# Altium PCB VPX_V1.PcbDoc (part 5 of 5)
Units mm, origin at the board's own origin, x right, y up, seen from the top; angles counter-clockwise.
Board outline 157.76 x 100.08 mm, 10 copper layers (Top Layer (PADS/SIG), Layer 2 (GND), Layer 3 (SIG), Layer 4 (SIG), Layer 5 (GND), Layer 6 (PWR), Layer 7 (GND), Layer 8 (SIG/PWR), Layer 9 (GND), Bottom Layer (PAD/SIG)), stack 1.614 mm thick; 383 components, 223 nets, 1313 pads, 1223 vias.
Unrouted connection lines stored in the file: 3.
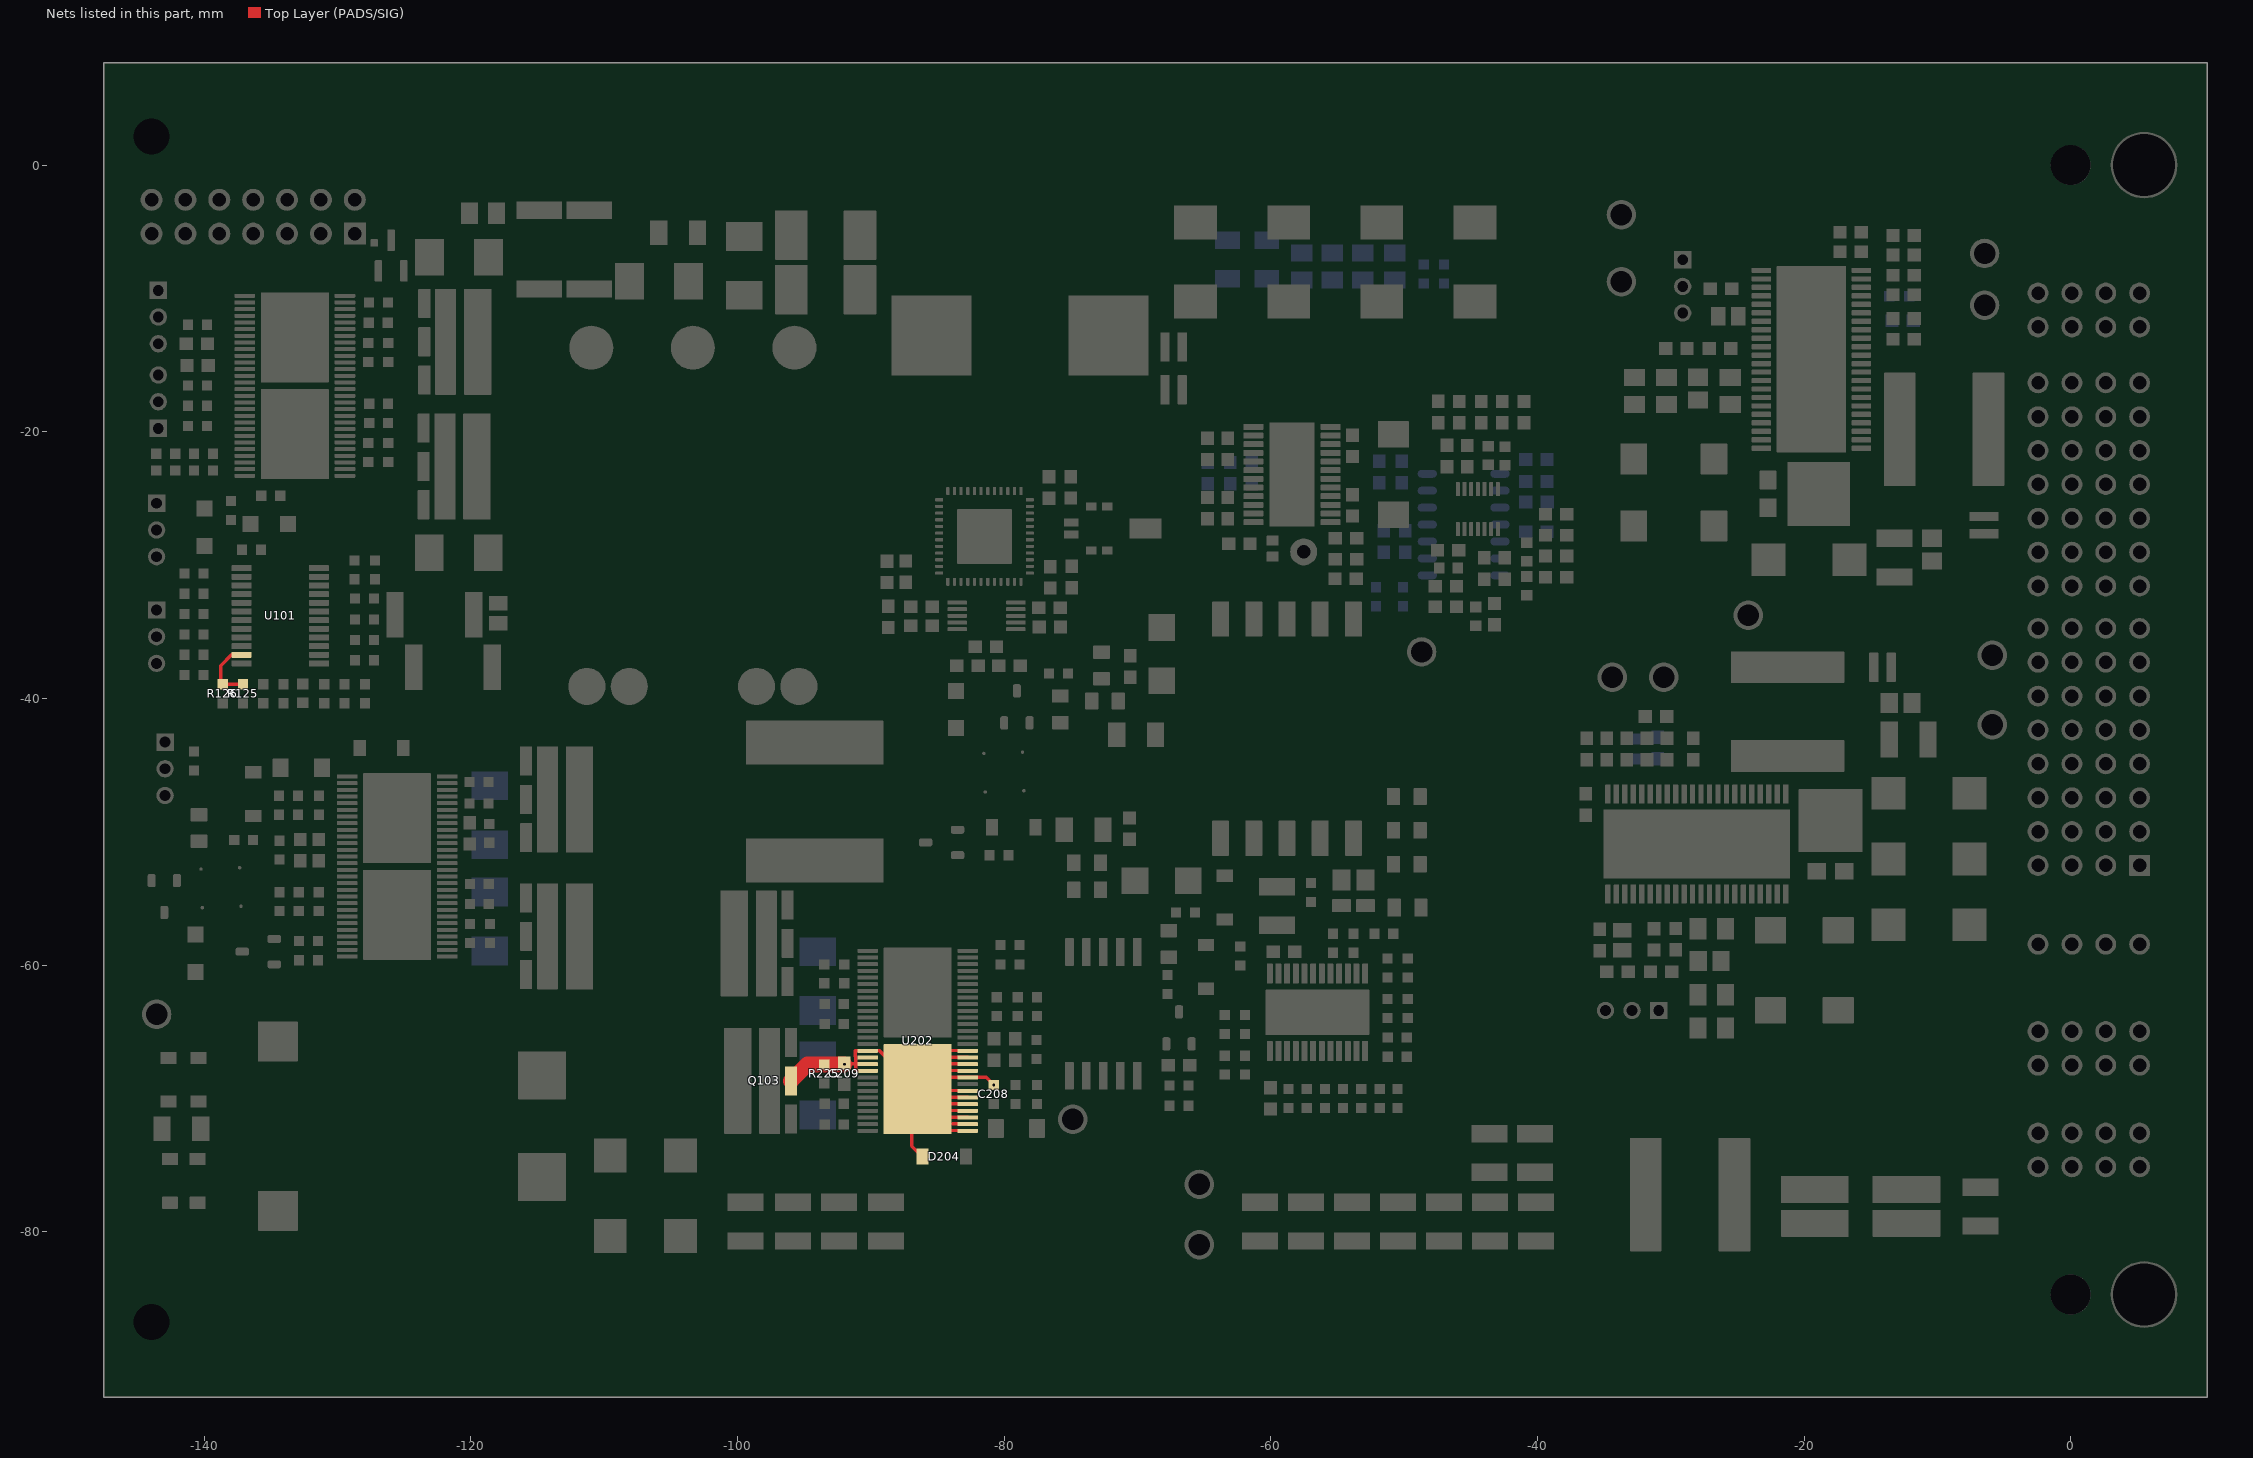
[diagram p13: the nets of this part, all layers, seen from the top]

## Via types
v1: diameter 0.508, hole 0.203, Top Layer (PADS/SIG) to Bottom Layer (PAD/SIG), 943 vias
v2: diameter 0.5, hole 0.2, Top Layer (PADS/SIG) to Bottom Layer (PAD/SIG), tented both sides, 268 vias
v3: diameter 0.5, hole 0.2, Top Layer (PADS/SIG) to Bottom Layer (PAD/SIG), 12 vias

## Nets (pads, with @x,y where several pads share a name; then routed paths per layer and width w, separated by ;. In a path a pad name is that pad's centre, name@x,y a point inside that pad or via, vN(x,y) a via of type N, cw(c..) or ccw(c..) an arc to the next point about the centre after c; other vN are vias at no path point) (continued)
VS_HOB: C208.2 C209.2 D204.2 Q103.5 R225.2 U202.1 U202.2 U202.3 U202.4 U202.5 U202.6 U202.7 U202.9 U202.10 U202.11 U202.12 U202.13 U202.44 U202.45 U202.46 U202.47 U202.57 | length 47.4
  Top Layer (PADS/SIG) w0.254: C209.2@-91.985,-67.446 v1(-91.966,-67.428) -91.946,-67.408 -91.12,-67.408 ; U202.47@-90.235,-67.908 -91.092,-67.908 -91.12,-67.879 -91.12,-67.408 ; U202.46@-90.235,-67.408 -91.12,-67.408 ; U202.57@-86.911,-70.806 -86.911,-73.573 D204.2@-86.122,-74.362 ; U202.57@-86.485,-69.283 -89.36,-66.408 -90.235,-66.408 -91.173,-66.408 -91.173,-66.855 -91.12,-66.908 -91.12,-67.408 ; U202.57@-86.36,-69.408 U202.7@-82.735,-69.408 ; U202.57@-85.86,-69.908 U202.6@-82.735,-69.908 ; U202.57@-85.36,-70.408 U202.5@-82.735,-70.408 ; U202.57@-84.86,-70.908 U202.4@-82.735,-70.908 ; U202.57@-84.61,-67.408 U202.11@-82.735,-67.408 ; U202.57@-84.371,-66.488 -84.291,-66.408 U202.13@-82.735,-66.408 ; U202.57@-84.36,-71.408 U202.3@-82.735,-71.408 ; U202.57@-84.11,-66.908 U202.12@-82.735,-66.908 ; U202.57@-84.032,-72.408 U202.1@-82.735,-72.408 ; -83.86,-71.908 U202.2@-82.735,-71.908 ; U202.10@-82.735,-67.908 -85.11,-67.908 -85.61,-68.408 -82.735,-68.408 -82.717,-68.426 -81.335,-68.426 v1(-80.775,-68.987) ; C208.2@-80.759,-68.971 -80.759,-69.002 -80.521,-69.241 C208.2@-80.49,-69.241
  Top Layer (PADS/SIG) w1.194: Q103.5@-95.979,-68.681 -94.744,-67.446 R225.2@-93.485,-67.446 C209.2@-91.985,-67.446
VSENSE: R125.1 R126.2 U101.23 | length 4.9
  Top Layer (PADS/SIG) w0.254: U101.23@-137.181,-36.731 -137.94,-36.731 -138.752,-37.544 -138.752,-38.785 R126.2@-138.599,-38.937 R125.1@-137.075,-38.937
pads on no net: "MSP430 JTAG.6" "MSP430 JTAG.12" "MSP430 JTAG.14" J1.A1 J1.A2 J1.A3 J1.A4 J1.A5 J1.A6 J1.A7 J1.A8 J1.B1 J1.B2 J1.B3 J1.B4 J1.B5 J1.B6 J1.B7 J1.B8 J1.C1 J1.C2 J1.C3 J1.C4 J1.C6 J1.C7 J1.C8 J1.D1 J1.D2 J1.D3 J1.D4 J1.D6 J1.D7 J1.D8 J2. J4. Q101.2 Q102.2 Q103.2 Q104.2 Q105.2 Q106.2 T1.3 T1.6 T1.7 T1.8 U1.7 U1.8 U1.9 U1.10 U1.11 U1.16 U1.17 U1.18 U1.19 U1.26 U1.27 U1.28 U1.29 U1.30 U1.33 U1.38 U1.39 U1.40 U1.42 U1.43 U1.49@-80.098,-26.483 U1.49@-80.098,-27.853 U1.49@-80.098,-29.223 U1.49@-81.468,-26.483 U1.49@-81.468,-27.853 U1.49@-81.468,-29.223 U1.49@-82.838,-26.483 U1.49@-82.838,-27.853 U1.49@-82.838,-29.223 U4.7 U4.9 U4.37 U7.7 U9.1 U9.8 U201.14 U201.16 U201.43 U202.14 U202.16 U202.43 U203.14 U203.16 U203.43

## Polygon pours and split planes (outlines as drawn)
PGND on Layer 9 (GND) "LAYER_9_(GND)_PGND_P079" (solid, remove dead copper, pour order 79): -1.717,-56.455 10.288,-56.455 10.288,-82.453 9.627,-83.114 -138.102,-83.114 -138.102,-56.4 -138.102,-42.408 -118.323,-42.408 -113.087,-37.104 -92.813,-37.104 -84.182,-45.735 -47.538,-45.735 -46.989,-46.284 -46.989,-71.612 -16.874,-71.612 -6.955,-61.692
SGND on Layer 9 (GND) "LAYER_9_(GND)_SGND_P064" (solid, remove dead copper, pour order 64): -0.406,-53.498 5.494,-53.498 5.494,-1.489 -145.204,-1.489 -145.204,-83.165 -139.278,-83.168 -139.108,-82.998 -139.108,-60.068 -139.108,-41.063 -119.189,-41.063 -114.151,-36.025 -93.117,-36.025 -84.422,-44.72 -46.83,-44.72 -45.89,-45.66 -45.89,-70.559 -17.467,-70.559 -8.171,-61.263
PGND on Top Layer (PADS/SIG) "TOP_LAYER_(PADS/SIG)_PGND_P080" (solid, remove dead copper, pour order 80): -1.754,-56.58 10.251,-56.58 10.251,-82.579 9.59,-83.239 -138.14,-83.239 -138.14,-56.525 -138.14,-42.533 -118.36,-42.533 -113.125,-37.23 -92.85,-37.23 -84.22,-45.86 -47.575,-45.86 -47.026,-46.409 -47.026,-71.12 -16.294,-71.12 -6.992,-61.818
Chassis on Top Layer (PADS/SIG) "TOP_LAYER_(PADS/SIG)_CHASSIS_P074" (solid, remove dead copper, pour order 74): 6.561,-53.026 6.307,-52.772 6.307,-1.333 10.117,-1.333 10.117,-56.654 10.216,-56.654 10.262,-56.7 10.262,-89.82 -147.617,-89.842 -147.617,5.33 10.233,5.33 10.262,5.3 10.262,-1.333 -145.331,-1.333 -145.331,-82.991 -3.264,-82.991 -3.159,-83.096 -3.159,-57.854 -1.981,-56.676 2.911,-56.676
3.3V on Top Layer (PADS/SIG) "TOP_LAYER_(PADS/SIG)_3.3V_P002" (solid, remove dead copper, pour order 2): -54.653,-18.863 -47.795,-18.863 -47.795,-22.8 -54.653,-22.8
PVIN on Top Layer (PADS/SIG) "TOP_LAYER_(PADS/SIG)_PVIN_P003" (solid, remove dead copper, pour order 3): -17.493,-70.646 -12.319,-65.472 -12.323,-56.593 -39.786,-56.593 -39.786,-70.646
SGND on Top Layer (PADS/SIG) "TOP_LAYER_(PADS/SIG)_SGND_P070" (solid, remove dead copper, pour order 70): -0.413,-53.526 5.488,-53.526 5.488,-1.517 -145.331,-1.517 -145.331,-83.193 -140.322,-83.196 -139.115,-83.175 -139.115,-60.096 -139.115,-41.091 -119.196,-41.091 -114.158,-36.053 -93.124,-36.053 -84.429,-44.748 -46.837,-44.748 -45.897,-45.688 -45.897,-70.587 -17.473,-70.587 -8.178,-61.291
"Input Return" on Top Layer (PADS/SIG) "TOP_LAYER_(PADS/SIG)_INPUT_RETURN_P068" (solid, remove dead copper, pour order 68): -15.156,-78.299 -4.869,-78.299 -4.869,-71.441 -4.996,-71.314 -4.488,-70.806 7.577,-70.806 7.577,-83.125 7.45,-83.252 -15.156,-83.252
Input_Supply on Top Layer (PADS/SIG) "TOP_LAYER_(PADS/SIG)_INPUT_SUPPLY_P065" (solid, remove dead copper, pour order 65): -15.156,-77.791 -15.156,-71.949 -15.029,-71.949 -2.202,-59.122 6.307,-59.122 6.307,-68.393 4.91,-69.79 -3.218,-69.79 -4.996,-71.568 -4.996,-77.791
3.3V_OUT on Top Layer (PADS/SIG) "TOP_LAYER_(PADS/SIG)_3.3V_OUT_P058" (solid, remove dead copper, pour order 58): -4.8,-35.692 6.815,-24.078 6.815,-14.896 -25.964,-14.896 -25.964,-35.692
"3.3V CS+" on Top Layer (PADS/SIG) "TOP_LAYER_(PADS/SIG)_3.3V_CS+_P057" (solid, remove dead copper, pour order 57): -10.82,-27.005 -10.82,-13.475 -4.768,-13.475 -4.768,-27.005
5V on Top Layer (PADS/SIG) "TOP_LAYER_(PADS/SIG)_5V_P027" (solid, remove dead copper, pour order 27): -12.323,-65.415 -12.323,-34.736 -3.178,-34.736 -3.178,-56.269 -8.171,-61.263
"5V CS+" on Top Layer (PADS/SIG) "TOP_LAYER_(PADS/SIG)_5V_CS+_P028" (solid, remove dead copper, pour order 28): -27.531,-40.025 -27.531,-34.471 -14.328,-34.471 -14.328,-40.025
VIN on Top Layer (PADS/SIG) "TOP_LAYER_(PADS/SIG)_VIN_P026" (solid, remove dead copper, pour order 26): -119.039,-81.28 -119.039,-71.632 -30.734,-71.632 -30.734,-81.28
NetL3_1 on Top Layer (PADS/SIG) "TOP_LAYER_(PADS/SIG)_NETL3_1_P025" (solid, remove dead copper, pour order 25): -29.972,-82.851 -29.972,-72.898 -15.631,-72.898 -15.631,-82.851
PVIN on Top Layer (PADS/SIG) "TOP_LAYER_(PADS/SIG)_PVIN_P024" (solid, remove dead copper, pour order 24): -38.362,-18.215 -38.362,-28.783 -37.533,-29.611 -21.887,-29.611 -21.887,-7.687 -68.316,-7.687 -68.316,-18.215
"12V CS+" on Top Layer (PADS/SIG) "TOP_LAYER_(PADS/SIG)_12V_CS+_P022" (solid, remove dead copper, pour order 22): -67.451,-22.15 -76.157,-22.15 -76.157,-3.369 -67.451,-3.369
NetD1_3 on Top Layer (PADS/SIG) "TOP_LAYER_(PADS/SIG)_NETD1_3_P021" (solid, remove dead copper, pour order 21): -21.637,-19.222 -21.637,-21.012 -21.637,-27.061 -11.213,-27.061 -11.213,-13.589 -16.549,-13.589 -16.549,-19.222
NetD2_3 on Top Layer (PADS/SIG) "TOP_LAYER_(PADS/SIG)_NETD2_3_P019" (solid, remove dead copper, pour order 19): -28.696,-47.824 -28.696,-46.034 -27.138,-46.034 -27.138,-43.995 -25.994,-42.851 -25.982,-42.863 -15.338,-42.863 -15.338,-51.745 -20.673,-51.745 -20.673,-47.824
SW_A on Top Layer (PADS/SIG) "TOP_LAYER_(PADS/SIG)_SW_A_P006" (solid, remove dead copper, pour order 6): -115.218,-39.35 -113.131,-37.264 -106.572,-37.264 -106.572,-41.133 -115.218,-41.133
NetD3_1 on Top Layer (PADS/SIG) "TOP_LAYER_(PADS/SIG)_NETD3_1_P018" (solid, remove dead copper, pour order 18): -112.946,-43.027 -112.946,-37.864 -102.035,-37.864 -101.721,-38.178 -101.721,-63.367 -99.771,-63.367 -98.879,-64.259 -98.879,-73.103 -118.457,-73.103 -118.948,-72.612 -118.948,-62.076 -110.306,-61.922 -110.306,-61.434 -110.306,-52.651 -111.995,-52.651 -113.2,-51.446
NetL301_2 on Top Layer (PADS/SIG) "TOP_LAYER_(PADS/SIG)_NETL301_2_P017" (solid, remove dead copper, pour order 17): -92.515,-37.735 -88.759,-41.491 -88.759,-45.248 -100.631,-45.248 -100.631,-37.735
NetC117_2 on Top Layer (PADS/SIG) "TOP_LAYER_(PADS/SIG)_NETC117_2_P016" (solid, remove dead copper, pour order 16): -117.653,-39.5 -116.925,-38.775 -116.925,-31.744 -121.272,-31.744 -121.272,-39.5
NetC117_1 on Top Layer (PADS/SIG) "TOP_LAYER_(PADS/SIG)_NETC117_1_P008" (solid, pour order 8): -120.964,-18.804 -120.323,-18.164 -120.323,-18.124 -99.253,-18.124 -99.23,-18.101 -99.484,-17.847 -99.484,-11.673 -100.109,-11.673 -101.734,-10.048 -101.734,-7.56 -95.895,-7.56 -91.71,-11.745 -91.71,-32.813 -118.158,-32.813 -120.964,-30.006 -120.964,-18.754
NetL101_1 on Top Layer (PADS/SIG) "TOP_LAYER_(PADS/SIG)_NETL101_1_P015" (solid, remove dead copper, pour order 15): -91.737,-19.59 -91.737,-9.551 -80.264,-9.551 -80.264,-19.59
NetL101_1 on Top Layer (PADS/SIG) "TOP_LAYER_(PADS/SIG)_NETL101_1_P014" (solid, remove dead copper, pour order 14): -106.385,-20.378 -106.385,-11.673 -99.484,-11.673 -99.484,-20.378
NetC118_1 on Top Layer (PADS/SIG) "TOP_LAYER_(PADS/SIG)_NETC118_1_P013" (solid, remove dead copper, pour order 13): -117.109,-2.077 -117.205,-2.173 -117.205,-11.14 -116.672,-11.673 -110.025,-11.673 -110.025,-8.517 -107.004,-5.537 -107.004,-17.419 -120.715,-17.419 -120.715,-2.077
NetC118_2 on Top Layer (PADS/SIG) "TOP_LAYER_(PADS/SIG)_NETC118_2_P012" (solid, remove dead copper, pour order 12): -118.661,-10.386 -118.661,-2.187 -108.882,-2.187 -108.882,-10.386
NetC122_1 on Top Layer (PADS/SIG) "TOP_LAYER_(PADS/SIG)_NETC122_1_P011" (solid, remove dead copper, pour order 11): -105.518,-11.511 -105.518,-2.806 -93.449,-2.806 -93.449,-11.511
NetC44_1 on Top Layer (PADS/SIG) "TOP_LAYER_(PADS/SIG)_NETC44_1_P001" (solid, remove dead copper, pour order 1): -73.195,-44.009 -73.195,-37.635 -66.429,-37.635 -66.429,-44.009
NetC49_1 on Top Layer (PADS/SIG) "TOP_LAYER_(PADS/SIG)_NETC49_1_P010" (solid, remove dead copper, pour order 10): -75.037,-54.629 -75.037,-48.931 -68.623,-48.931 -68.623,-54.629
Input_Supply on Layer 8 (SIG/PWR) "LAYER_8_(SIG/PWR)_INPUT_SUPPLY_P071" (solid, remove dead copper, pour order 71): -34.46,-71.695 -16.934,-71.695 -1.821,-56.582 9.609,-56.582 9.609,-82.871 9.228,-83.252 -34.46,-83.252
VIN on Layer 8 (SIG/PWR) "LAYER_8_(SIG/PWR)_VIN_P054" (solid, remove dead copper, pour order 54): -31.482,-83.252 -138.146,-83.252 -138.146,-56.538 -138.146,-42.547 -118.367,-42.547 -113.131,-37.243 -92.857,-37.243 -84.226,-45.873 -47.582,-45.873 -47.033,-46.422 -47.033,-71.75 -31.609,-71.75
PVIN on Layer 8 (SIG/PWR) "LAYER_8_(SIG/PWR)_PVIN_P041" (solid, remove dead copper, pour order 41): -46.83,-44.72 -45.89,-45.66 -45.89,-70.559 -17.467,-70.559 -8.171,-61.263 -32.932,-61.263 -33.53,-60.666 -33.53,-28.497 9.609,-28.348 9.609,-1.502 9.597,-1.489 9.476,-1.61 -145.519,-1.61 -145.193,-83.057 -139.108,-83.057 -139.108,-60.068 -139.108,-41.096 -119.223,-41.096 -114.151,-36.025 -93.117,-36.025 -84.422,-44.72
3.3V_OUT on Layer 8 (SIG/PWR) "LAYER_8_(SIG/PWR)_3.3V_OUT_P039" (solid, remove dead copper, pour order 39): -3.21,-28.436 -6.824,-28.436 -14.569,-36.181 -15.171,-36.181 -33.564,-36.181 -33.564,-13.859 9.576,-13.859 9.576,-27.691 -2.608,-27.691 -3.21,-28.294
5V on Layer 8 (SIG/PWR) "LAYER_8_(SIG/PWR)_5V_P040" (solid, remove dead copper, pour order 40): -33.802,-27.768 -33.802,-61.263 -8.171,-61.263 -0.406,-53.498 9.597,-53.498 9.597,-27.768
SGND on Bottom Layer (PAD/SIG) "BOTTOM_LAYER_(PAD/SIG)_SGND_P062" (solid, remove dead copper, pour order 62): -0.406,-53.498 5.494,-53.498 5.494,-1.489 -145.458,-1.489 -145.458,-83.165 -139.278,-83.168 -139.108,-82.998 -139.108,-60.068 -139.108,-41.063 -119.189,-41.063 -114.151,-36.025 -93.117,-36.025 -84.422,-44.72 -46.83,-44.72 -45.89,-45.66 -45.89,-70.559 -17.467,-70.559 -8.171,-61.263
Chassis on Bottom Layer (PAD/SIG) "BOTTOM_LAYER_(PAD/SIG)_CHASSIS_P056" (solid, remove dead copper, pour order 56): 6.561,-53.026 6.307,-52.772 6.307,-1.333 10.117,-1.333 10.117,-56.654 10.216,-56.654 10.262,-56.7 10.262,-89.82 -147.617,-89.842 -147.617,5.33 10.233,5.33 10.262,5.3 10.262,-1.333 -145.204,-1.333 -145.204,-82.991 -3.264,-82.991 -3.159,-83.096 -3.159,-57.854 -1.981,-56.676 2.911,-56.676
PGND on Bottom Layer (PAD/SIG) "BOTTOM_LAYER_(PAD/SIG)_PGND_P067" (solid, remove dead copper, pour order 67): -1.762,-56.593 10.243,-56.593 10.243,-82.591 9.583,-83.252 -138.092,-83.252 -138.092,-42.546 -118.367,-42.546 -113.132,-37.243 -92.857,-37.243 -84.227,-45.873 -47.583,-45.873 -47.034,-46.422 -47.034,-71.75 -16.918,-71.75 -6.999,-61.831
NetL101_1 on Bottom Layer (PAD/SIG) "BOTTOM_LAYER_(PAD/SIG)_NETL101_1_P038" (solid, remove dead copper, pour order 38): -106.385,-20.42 -106.385,-11.662 -80.264,-11.662 -80.264,-20.42
3.3V on Layer 6 (PWR) "LAYER_6_(PWR)_3.3V_P037" (solid, remove dead copper, pour order 37): -68.978,-36.341 -68.48,-35.843 -68.48,-24.197 -38.288,-24.197 -38.232,-17.377 -39.54,-16.069 -88.506,-16.069 -88.506,-33.524 -85.64,-36.39
Input_Supply on Layer 6 (PWR) "LAYER_6_(PWR)_INPUT_SUPPLY_P073" (solid, remove dead copper, pour order 73): -34.46,-71.695 -16.934,-71.695 -1.821,-56.582 9.609,-56.582 9.609,-82.871 9.228,-83.252 -34.46,-83.252
+12Vp on Layer 6 (PWR) "LAYER_6_(PWR)_+12VP_P072" (solid, remove dead copper, pour order 72): -31.482,-83.252 -138.146,-83.252 -138.146,-56.538 -138.146,-42.547 -118.367,-42.547 -113.131,-37.243 -92.857,-37.243 -84.226,-45.873 -47.582,-45.873 -47.033,-46.422 -47.033,-71.75 -31.609,-71.75
5V on Layer 6 (PWR) "LAYER_6_(PWR)_5V_P046" (solid, remove dead copper, pour order 46): -26.713,-27.768 -26.713,-62.297 -9.205,-62.297 -8.171,-61.263 -0.406,-53.498 9.597,-53.498 9.597,-27.768
+12Vs on Layer 6 (PWR) "LAYER_6_(PWR)_+12VS_P020" (solid, remove dead copper, pour order 20): -42.334,-44.72 -42.334,-22.863 -60.02,-22.863 -62.491,-20.393 -68.077,-20.393 -68.396,-20.712 -68.396,-36.344 -85.686,-36.344 -88.698,-33.332 -88.698,-1.702 -145.458,-1.702 -145.458,-82.998 -139.108,-82.998 -139.108,-60.068 -139.108,-41.063 -119.189,-41.063 -114.151,-36.025 -93.244,-36.025 -84.549,-44.72
PVIN on Layer 6 (PWR) "LAYER_6_(PWR)_PVIN_P048" (solid, remove dead copper, pour order 48): -86.836,-42.433 -84.498,-44.771 -46.779,-44.771 -45.89,-45.66 -45.89,-70.607 -17.497,-70.607 -0.551,-53.661 9.609,-53.661 9.609,-1.502 9.597,-1.489 9.476,-1.61 -88.702,-1.61
3.3V_OUT on Layer 6 (PWR) "LAYER_6_(PWR)_3.3V_OUT_P047" (solid, remove dead copper, pour order 47): -3.178,-28.499 -6.791,-28.499 -14.536,-36.245 -15.138,-36.245 -26.713,-36.245 -26.713,-13.923 9.609,-13.923 9.609,-27.755 -2.575,-27.755 -3.178,-28.358
PGND on Layer 5 (GND) "LAYER_5_(GND)_PGND_P077" (solid, remove dead copper, pour order 77): -1.774,-56.517 10.231,-56.517 10.231,-82.515 9.571,-83.176 -138.159,-83.176 -138.159,-56.462 -138.159,-42.47 -118.379,-42.47 -113.144,-37.167 -92.869,-37.167 -84.239,-45.797 -47.595,-45.797 -47.046,-46.346 -47.046,-71.674 -16.93,-71.674 -7.011,-61.754
SGND on Layer 5 (GND) "LAYER_5_(GND)_SGND_P061" (solid, remove dead copper, pour order 61): -0.406,-53.498 5.494,-53.498 5.494,-1.489 -145.331,-1.489 -145.331,-83.165 -139.108,-83.169 -139.108,-60.068 -139.108,-41.063 -119.189,-41.063 -114.151,-36.025 -93.117,-36.025 -84.422,-44.72 -46.83,-44.72 -45.89,-45.66 -45.89,-70.559 -17.467,-70.559 -8.171,-61.263
PGND on Layer 7 (GND) "LAYER_7_(GND)_PGND_P078" (solid, remove dead copper, pour order 78): -1.732,-56.474 10.273,-56.474 10.273,-82.472 9.613,-83.133 -138.117,-83.133 -138.117,-56.419 -138.117,-42.427 -118.338,-42.427 -113.102,-37.123 -92.827,-37.123 -84.197,-45.754 -47.553,-45.754 -47.004,-46.303 -47.004,-71.631 -16.889,-71.631 -6.969,-61.711
SGND on Layer 7 (GND) "LAYER_7_(GND)_SGND_P063" (solid, remove dead copper, pour order 63): -0.406,-53.498 5.494,-53.498 5.494,-1.489 -145.331,-1.489 -145.331,-83.165 -139.235,-83.168 -139.235,-59.941 -139.235,-41.063 -119.189,-41.063 -114.151,-36.025 -93.117,-36.025 -84.422,-44.72 -46.83,-44.72 -45.89,-45.66 -45.89,-70.559 -17.467,-70.559 -8.171,-61.263
PGND on Layer 3 (SIG) "LAYER_3_(SIG)_PGND_P066" (solid, remove dead copper, pour order 66): -1.761,-56.593 10.244,-56.593 10.244,-82.592 9.584,-83.252 -138.146,-83.252 -138.146,-56.538 -138.146,-42.547 -118.367,-42.547 -113.131,-37.243 -92.857,-37.243 -84.226,-45.873 -47.582,-45.873 -47.033,-46.422 -47.033,-71.75 -16.918,-71.75 -6.998,-61.831
SGND on Layer 3 (SIG) "LAYER_3_(SIG)_SGND_P059" (solid, remove dead copper, pour order 59): -0.406,-53.549 5.494,-53.549 5.494,-1.54 -145.331,-1.54 -145.331,-83.215 -139.108,-83.219 -139.108,-60.119 -139.108,-41.113 -119.189,-41.113 -114.151,-36.075 -93.117,-36.075 -84.422,-44.771 -46.83,-44.771 -45.89,-45.711 -45.89,-70.609 -17.467,-70.609 -8.171,-61.314
PGND on Layer 4 (SIG) "LAYER_4_(SIG)_PGND_P076" (solid, remove dead copper, pour order 76): -1.767,-56.531 10.238,-56.531 10.238,-82.529 9.578,-83.19 -138.152,-83.19 -138.152,-56.476 -138.152,-42.484 -118.372,-42.484 -113.137,-37.18 -92.862,-37.18 -84.232,-45.811 -47.588,-45.811 -47.039,-46.36 -47.039,-71.688 -16.923,-71.688 -7.004,-61.768
SGND on Layer 4 (SIG) "LAYER_4_(SIG)_SGND_P060" (solid, remove dead copper, pour order 60): -0.406,-53.498 5.494,-53.498 5.494,-1.489 -145.458,-1.489 -145.458,-83.165 -139.108,-83.169 -139.108,-60.068 -139.108,-41.063 -119.189,-41.063 -114.151,-36.025 -93.117,-36.025 -84.422,-44.72 -46.83,-44.72 -45.89,-45.66 -45.89,-70.559 -17.467,-70.559 -8.171,-61.263
PGND on Layer 2 (GND) "LAYER_2_(GND)_PGND_P075" (solid, remove dead copper, pour order 75): -1.752,-56.585 10.253,-56.585 10.253,-82.583 9.592,-83.243 -138.137,-83.243 -138.137,-56.53 -138.137,-42.538 -118.358,-42.538 -113.122,-37.234 -92.848,-37.234 -84.217,-45.864 -47.573,-45.864 -47.024,-46.413 -47.024,-71.741 -16.909,-71.741 -6.99,-61.822
SGND on Layer 2 (GND) "LAYER_2_(GND)_SGND_P053" (solid, remove dead copper, pour order 53): -0.406,-53.498 5.494,-53.498 5.494,-1.489 -145.331,-1.489 -145.331,-83.165 -139.151,-83.169 -139.108,-83.125 -139.108,-41.063 -119.189,-41.063 -114.151,-36.025 -93.117,-36.025 -84.422,-44.72 -46.83,-44.72 -45.89,-45.66 -45.89,-70.559 -17.467,-70.559 -8.171,-61.263

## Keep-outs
Keep-Out Layer:
  text ".Layer_Name" at -195.191,-114.202 h1.52

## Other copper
Top Layer (PADS/SIG):
  region net NetR55_1: -54.812,-61.411 -54.812,-58.617 -55.701,-58.617 -55.701,-61.411
  region net NetR51_1: -53.418,-61.411 -53.418,-58.617 -54.434,-58.617 -54.434,-61.411
  region net VLDO: -58.879,-61.411 -57.609,-61.411 -57.609,-59.684 -58.133,-59.159 -58.456,-59.159 -58.879,-59.598
  text ".Layer_Name" at -195.191,-114.202 h1.52
Bottom Layer (PAD/SIG):
  text ".Layer_Name" at -195.191,-114.202 h1.52

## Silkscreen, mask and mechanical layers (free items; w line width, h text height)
Top Overlay:
  lines w0.254: -147.515,-89.602 -147.515,5.133 ; -147.39,5.14 -3.164,5.116 ; -147.345,-83.087 -3.174,-83.176 ; -147.246,-89.856 -3.177,-89.851 ; -147.109,-1.629 -3.136,-1.651
  text "'.PRJ_Number'.PCB_Rev" at -122.471,-86.681 h3.05
  text ".Layer_Name" at -195.191,-114.202 h1.52
Bottom Overlay:
  text ".Layer_Name" at -195.191,-114.202 h1.52
Top Paste:
  text ".Layer_Name" at -195.191,-114.202 h1.52
Bottom Paste:
  text ".Layer_Name" at -195.191,-114.202 h1.52
Top Solder:
  text ".Layer_Name" at -195.191,-114.202 h1.52
  text ".Layer_Name" at -195.191,-114.202 h1.52
Bottom Solder:
  text ".Layer_Name" at -195.191,-114.202 h1.52
Drill Guide:
  text ".Layer_Name" at -195.191,-114.202 h1.52
M1 Board Outline:
  lines w0.254: -147.54,7.642 10.117,7.642 ; -147.526,-92.358 10.244,-92.358 ; -147.515,-92.396 -147.515,7.68 ; 10.244,-92.362 10.244,-71.505 10.244,-30.23 10.244,7.68
  text ".Layer_Name" at -195.191,-114.202 h1.52
M2 Board Dimensions:
  rectangle: -209.847,-99.381 -206.672,-96.206
  rectangle: -206.672,-102.556 -197.147,-99.381
  lines w0.178: -209.847,-99.381 -184.447,-99.381 ; -206.672,-102.556 -206.672,-96.206 ; -203.497,-102.556 -203.497,-96.206 ; -197.147,-102.556 -197.147,-96.206 ; -190.797,-102.556 -190.797,-96.206 ; -209.847,-102.556 -184.447,-102.556 -184.447,-96.206 -209.847,-96.206 -209.847,-102.556
  lines w0.254: -147.479,0.035 10.117,0.035
  text "0.00" at 3.64,8.315 h1.02 r90
  text "0.00" at 21.801,0.314 h1.02
  text ".Layer_Name" at -195.191,-114.202 h1.52
M3 3D STEP Top:
  text ".Layer_Name" at -195.191,-114.202 h1.52
M4 3D STEP Bottom:
  text ".Layer_Name" at -195.191,-114.202 h1.52
M5 Assembly Top:
  lines w0.254: -217.264,-116.022 -49.624,-116.022 ; -217.264,-110.858 -49.573,-110.858 ; -217.264,-105.693 -217.264,-121.187 -115.537,-121.187 -49.573,-121.187 -49.573,-105.693 -217.251,-105.693 -217.251,-121.187 -177.233,-121.187 ; -154.653,-121.187 -154.653,-105.693 ; -122.471,-110.858 -122.471,-105.693 ; -101.135,-110.858 -101.135,-105.693 ; -85.336,-121.352 -85.336,-116.2
  text "COMPONENTS MARKED 'DNP' SHOULD NOT BE POPULATED." at -180.548,-100.486 h1.02
  text "ASSEMBLY VARIANT:" at -180.561,-103.42 h1.02
  text ".VariantName" at -154.246,-103.42 h1.02
  text "PCB VIEWED FROM TOP SIDE" at -215.651,-109.05 h1.52
  text "BOARD #:" at -152.748,-109.05 h1.52
  text ".PRJ_Number" at -138.892,-109.05 h1.52
  text "REV:" at -117.442,-109.05 h1.52
  text ".PCB_Rev" at -110.038,-109.05 h1.52
  text "SVN REV:" at -96.157,-109.05 h1.52
  text ".VersionControl_RevNumber" at -83.304,-109.05 h1.52
  text "TID #:" at -152.748,-114.215 h1.52
  text ".TID" at -138.892,-114.215 h1.52
  text "PLOT NAME =" at -215.651,-119.43 h1.52
  text ".plot_File_Name" at -195.191,-119.43 h1.52
  text "GENERATED    :" at -152.697,-119.43 h1.52
  text ".Print_Date" at -130.612,-119.43 h1.52
  text ".Print_Time" at -112.095,-119.43 h1.52
  text "TEXAS INSTRUMENTS" at -79.977,-119.43 h1.52
M6 Assembly Bottom:
  lines w0.254: -217.276,-110.87 -49.586,-110.87 ; -217.226,-116.035 -49.586,-116.035 ; -181.513,-121.365 -181.513,-116.213 ; -165.714,-110.87 -165.714,-105.706 ; -144.378,-110.87 -144.378,-105.706 ; -112.197,-121.2 -112.197,-105.706 ; -89.616,-121.2 -49.598,-121.2 -49.598,-105.706 -217.276,-105.706 -217.276,-121.2 -151.313,-121.2 -49.586,-121.2 -49.586,-105.706
  text "COMPONENTS MARKED 'DNP' SHOULD NOT BE POPULATED." at -54.856,-100.473 h1.02
  text ".VariantName" at -81.374,-103.42 h1.02
  text "ASSEMBLY VARIANT:" at -54.983,-103.42 h1.02
  text ".VersionControl_RevNumber" at -183.545,-109.063 h1.52
  text "SVN REV:" at -170.693,-109.063 h1.52
  text ".PCB_Rev" at -156.812,-109.063 h1.52
  text "REV:" at -149.408,-109.063 h1.52
  text ".PRJ_Number" at -127.957,-109.063 h1.52
  text "BOARD #:" at -114.102,-109.063 h1.52
  text "PCB VIEWED FROM BOTTOM SIDE" at -51.199,-109.063 h1.52
  text ".TID" at -127.957,-114.227 h1.52
  text "TID #:" at -114.102,-114.227 h1.52
  text "TEXAS INSTRUMENTS" at -186.873,-119.443 h1.52
  text ".Print_Time" at -154.754,-119.443 h1.52
  text ".Print_Date" at -136.238,-119.443 h1.52
  text "GENERATED    :" at -114.152,-119.443 h1.52
  text ".plot_File_Name" at -71.658,-119.443 h1.52
  text "PLOT NAME =" at -51.199,-119.443 h1.52
M9 Title Sheet:
  drawing of 57 lines, arcs and shapes, not listed
  text "1" at -191.055,111.731 h1.78
  text "2" at -127.665,111.731 h1.78
  text "3" at -64.436,111.731 h1.78
  text "4" at -0.767,111.731 h1.78
  text "5" at 62.708,111.731 h1.78
  text "6" at 126.335,111.731 h1.78
  text "A" at -220.426,82.699 h1.78
  text "A" at 155.494,82.699 h1.78
  text "B" at -220.426,22.247 h1.78
  text "B" at 155.494,22.247 h1.78
  text "C" at -220.426,-38.078 h1.78
  text "C" at 155.494,-38.078 h1.78
  text "PROJECT TITLE:" at 78.278,-85.348 h1.14
  text ".PRJ_Title" at 79.548,-88.734 h1.78
  text "DESIGNED FOR:" at 78.278,-92.993 h1.14
  text ".PRJ_Customer" at 79.548,-96.549 h1.78
  text "D" at -220.426,-98.276 h1.78
  text "D" at 155.494,-98.276 h1.78
  text "FILE NAME:" at 78.278,-100.613 h1.14
  text ".PCB_File_Name_No_Path" at 79.548,-103.661 h1.78
  text "Texas Instruments (TI) and/or its licensors do not warrant the accuracy or completeness of this specification" at -47.947,-107.772 h1.14
  text "ENGINEER:" at 78.278,-107.979 h1.14
  text "LAYOUT BY:" at 116.505,-107.979 h1.14
  text "or any information contained therein. TI and/or its licensors do not warrant that this design will meet" at -49.09,-110.633 h1.14
  text ".PRJ_Engineer" at 79.548,-111.916 h1.78
  text ".PCB_Layout" at 117.788,-111.916 h1.78
  text "the specifications, will be suitable for your application or fit for any particular purpose, or will operate in" at -49.09,-113.495 h1.14
  text ".Layer_Name" at -195.191,-114.202 h1.52
  text "ALTIUM DESIGNER VERSION:" at 116.505,-115.853 h1.14
  text "an implementation. TI and/or its licensors do not warrant that the design is production worthy. You should" at -49.09,-116.357 h1.14
  text "completely validate and test your design implementation to confirm the system functionality for your application." at -47.947,-119.218 h1.14
  text ".print_Scale" at 79.548,-119.239 h1.78
  text ".Application_BuildNumber" at 117.788,-119.239 h1.78
  text "1" at -191.055,-124.489 h1.78
  text "2" at -127.665,-124.489 h1.78
  text "3" at -64.436,-124.489 h1.78
  text "4" at -0.767,-124.489 h1.78
  text "5" at 62.708,-124.489 h1.78
  text "6" at 126.335,-124.489 h1.78
M10 Fab Notes:
  drawing of 189 lines, arcs and shapes, not listed
  text "DESIGN INFORMATION" at 104.656,69.051 h1.52
  text "MIN. TRACK WIDTH:" at 88.284,65.695 h1.52
  text "8" at 116.129,65.695 h1.52
  text "MIL" at 120.06,65.695 h1.52
  text "7.874" at 111.903,62.604 h1.52
  text "MIN. CLEARANCE:" at 88.284,62.542 h1.52
  text "MIL" at 120.06,62.542 h1.52
  text "MIN. VIA PAD SIZE:" at 88.284,59.389 h1.52
  text "24" at 115.367,59.389 h1.52
  text "MIL" at 120.06,59.389 h1.52
  text "0.05mm (2MIL)" at 105.937,56.09 h1.52
  text "MINIMUM ANNULAR RING" at 79.922,55.881 h1.52
  text "EXTERNAL" at 123.921,55.881 h1.52
  text "PER" at 85.002,53.084 h1.52
  text "IPC-D-275 CLASS 2 LEVEL C" at 90.59,53.084 h1.52
  text "MIL, HOLES" at 128.391,50.531 h1.52
  text "+/-" at 118.423,50.313 h1.52
  text "+/-" at 140.114,50.313 h1.52
  text "REGISTRATION TOLERANCES:" at 79.922,50.286 h1.52
  text "METAL" at 110.396,50.286 h1.52
  text "5" at 125.032,50.286 h1.52
  text "3" at 146.19,50.286 h1.52
  text "MIL" at 149.143,50.286 h1.52
  text "HOLE SIZE TOLERANCE (UNLESS OTHERWISE SPECIFIED):" at 79.922,47.789 h1.52
  text "+/-" at 140.114,47.716 h1.52
  text "3" at 146.19,47.689 h1.52
  text "MIL" at 149.143,47.689 h1.52
  text "MATERIAL:" at 78.023,44.193 h1.52
  text "FR-4 High Tg" at 103.079,40.928 h1.52
  text "FR-4" at 88.716,40.611 h1.52
  text "OTHER" at 126.511,40.611 h1.52
  text "62 MIL (1.6mm) +/-10%" at 96.847,36.978 h1.52
  text "THICKNESS:" at 79.922,36.769 h1.52
  text "OTHER" at 129.483,36.769 h1.52
  text "TOLERANCE:" at 79.922,33.256 h1.52
  text "ANSI IPC-6012 TYPE 3 CLASS 2" at 105.989,33.256 h1.52
  text "OTHER +/-" at 105.988,29.593 h1.52
  text "BOW & TWIST:" at 79.922,25.906 h1.52
  text "ANSI IPC-6012 TYPE 3 CLASS 2" at 105.989,25.906 h1.52
  text "OTHER +/-" at 105.988,22.179 h1.52
  text "DRILLING:" at 78.023,18.862 h1.52
  text "NC_DRILL FILES" at 122.752,16.19 h1.52
  text "REFERENCE:" at 79.922,16.09 h1.52
  text "AS SHOWN" at 101.137,16.09 h1.52
  text "OTHER" at 130.321,12.477 h1.52
  text "PTH COPPER THICKNESS:" at 79.914,12.387 h1.52
  text "20-30 um" at 112.101,12.387 h1.52
  text "BOARD FINISH:" at 78.023,8.638 h1.52
  text "SILKSCREEN:" at 81.966,5.841 h1.52
  text "TOP" at 109.265,5.841 h1.52
  text "BOTTOM" at 122.244,5.841 h1.52
  text "SILKSCREEN COLOR:" at 81.966,1.899 h1.52
  text "WHITE" at 109.265,1.899 h1.52
  text "OTHER" at 122.244,1.899 h1.52
  text "GREEN" at 112.592,-1.744 h1.52
  text "OTHER" at 128.289,-1.744 h1.52
  text "SOLDER RESIST COLOR:" at 81.966,-1.919 h1.52
  text "MATTE" at 112.592,-5.662 h1.52
  text "SEMI-GLOSS" at 128.278,-5.679 h1.52
  text "IMMERSION GOLD (ENIG)" at 104.972,-10.051 h1.52
  text "ENEPIG" at 138.946,-10.234 h1.52
  text "SURFACE FINISH:" at 78.023,-10.26 h1.52
  text "IMM. TIN/SILVER OR EQUIV" at 86.393,-13.747 h1.52
  text "OTHER" at 122.752,-13.847 h1.52
  text "ARRAY/PANEL:" at 78.023,-17.794 h1.52
  text "CUT AND TRIM PER M1 BOARD OUTLINE" at 104.972,-18.003 h1.52
  text "N.C. ROUTE" at 104.972,-21.456 h1.52
  text "V. SCORE" at 126.969,-21.456 h1.52
  text "CERTIFICATION:" at 78.023,-24.736 h1.52
  text "MATERIALS AND WORKMANSHIP FOR ALL PCBS" at 96.438,-24.736 h1.52
  text "TO MEET OR EXCEED THE REQUIREMENTS OF:" at 96.438,-27.125 h1.52
  text "ANSI IPC-A-600F CLASS ->" at 90.482,-30.393 h1.52
  text "2" at 135.135,-30.393 h1.52
  text "1" at 127.134,-30.431 h1.52
  text "3" at 144.126,-30.431 h1.52
  text "RoHS" at 111.106,-34.144 h1.52
  text "OTHER" at 127.474,-34.144 h1.52
  text "PER ORDER" at 137.56,-34.144 h1.52
  text "ALL BOARDS MUST MEET OR EXCEED UL94-V0 REQUIREMENTS." at 78.722,-38.051 h1.52
  text "PCB MUST BEAR THE UL94V-0 UL REGISTERED MATERIAL ID NUMBER" at 78.722,-40.999 h1.52
  text "ADDITIONAL REQUIREMENTS:" at 78.023,-45.302 h1.52
  text "MICROSECTION:" at 79.922,-48.023 h1.52
  text "YES" at 102.928,-48.023 h1.52
  text "REQUIRED" at 124.81,-51.69 h1.52
  text "BARE BOARD ELEC. TEST:" at 79.922,-51.762 h1.52
  text "NONE" at 113.088,-51.762 h1.52
  text "PER ORDER" at 139.846,-51.762 h1.52
  text "XX MIL VIAS REQUIRE NON-CONDUCTIVE FILL AND PLANARIZE" at 84.193,-56.968 h1.5
  text "XX MIL VIAS REQUIRE CONDUCTIVE FILL AND PLANARIZE" at 84.396,-59.609 h1.52
  text "OUTER XX MIL TRACES REQUIRE 50 OHM SINGLE-ENDED IMPEDANCE" at 84.371,-63.759 h1.47
  text "LAYER 2 & 3 (INNER LAYERS) XX MIL WIDE, XX MIL SPACE / TRACES REQUIRE 100 OHM DIFFERENTIAL IMPEDANCE" at 84.168,-69.746 h1.52
  text ".Layer_Name" at -195.191,-114.202 h1.52
M11 Gerber Information:
  lines w0.254: -217.264,-116.022 -49.624,-116.022 ; -217.264,-110.858 -49.573,-110.858 ; -217.264,-105.693 -217.264,-121.187 -115.537,-121.187 -49.573,-121.187 -49.573,-105.693 -217.251,-105.693 -217.251,-121.187 -177.233,-121.187 ; -154.653,-121.187 -154.653,-105.693 ; -122.471,-110.858 -122.471,-105.693 ; -101.135,-110.858 -101.135,-105.693 ; -85.336,-121.352 -85.336,-116.2
  text "ALL ARTWORK VIEWED FROM TOP SIDE" at -215.651,-109.05 h1.52
  text "BOARD #:" at -152.748,-109.05 h1.52
  text ".PRJ_Number" at -138.892,-109.05 h1.52
  text "REV:" at -117.442,-109.05 h1.52
  text ".PCB_Rev" at -110.038,-109.05 h1.52
  text "SVN REV:" at -96.157,-109.05 h1.52
  text ".VersionControl_RevNumber" at -83.304,-109.05 h1.52
  text "LAYER NAME =" at -215.651,-114.202 h1.52
  text "TID #:" at -152.748,-114.215 h1.52
  text ".TID" at -138.892,-114.215 h1.52
  text "PLOT NAME =" at -215.651,-119.43 h1.52
  text ".plot_File_Name" at -195.191,-119.43 h1.52
  text "GENERATED    :" at -152.697,-119.43 h1.52
  text ".Print_Date" at -130.612,-119.43 h1.52
  text ".Print_Time" at -112.095,-119.43 h1.52
  text "TEXAS INSTRUMENTS" at -79.977,-119.43 h1.52
M12 Stackup:
  drawing of 607 lines, arcs and shapes, not listed
  text "Layer" at -201.118,97.469 h1.02
  text "Name" at -194.008,97.469 h1.02
  text "Material" at -170.477,97.469 h1.02
  text "Thickness" at -155.749,97.469 h1.02
  text "Constant" at -144.576,97.469 h1.02
  text "Board Layer Stack" at -134.757,97.469 h1.02
  text "Top Overlay" at -194.008,95.437 h1.02
  text "Top Solder" at -194.008,93.405 h1.02
  text "Solder Resist" at -170.477,93.405 h1.02
  text "0.40mil" at -155.749,93.405 h1.02
  text "3.5" at -144.576,93.405 h1.02
  text "1" at -201.118,91.373 h1.02
  text "Top Layer (PADS/SIG)" at -194.008,91.373 h1.02
  text "CF-004" at -170.477,91.373 h1.02
  text "2.76mil" at -155.749,91.373 h1.02
  text "Dielectric 1" at -194.008,89.341 h1.02
  text "PP-016" at -170.477,89.341 h1.02
  text "4.60mil" at -155.749,89.341 h1.02
  text "4.4" at -144.576,89.341 h1.02
  text "2" at -201.118,87.309 h1.02
  text "Layer 2 (GND)" at -194.008,87.309 h1.02
  text "CF-004" at -170.477,87.309 h1.02
  text "1.38mil" at -155.749,87.309 h1.02
  text "Dielectric 2" at -194.008,85.277 h1.02
  text "FR-4 High TG" at -170.477,85.277 h1.02
  text "6.00mil" at -155.749,85.277 h1.02
  text "4.5" at -144.576,85.277 h1.02
  text "3" at -201.118,83.245 h1.02
  text "Layer 3 (SIG)" at -194.008,83.245 h1.02
  text "CF-004" at -170.477,83.245 h1.02
  text "1.38mil" at -155.749,83.245 h1.02
  text "Dielectric 3" at -194.008,81.213 h1.02
  text "PP-016" at -170.477,81.213 h1.02
  text "4.60mil" at -155.749,81.213 h1.02
  text "4.4" at -144.576,81.213 h1.02
  text "4" at -201.118,79.181 h1.02
  text "Layer 4 (SIG)" at -194.008,79.181 h1.02
  text "CF-004" at -170.477,79.181 h1.02
  text "1.38mil" at -155.749,79.181 h1.02
  text "Dielectric 4" at -194.008,77.149 h1.02
  text "FR-4 High TG" at -170.477,77.149 h1.02
  text "6.00mil" at -155.749,77.149 h1.02
  text "4.5" at -144.576,77.149 h1.02
  text "5" at -201.118,75.117 h1.02
  text "Layer 5 (GND)" at -194.008,75.117 h1.02
  text "CF-004" at -170.477,75.117 h1.02
  text "1.38mil" at -155.749,75.117 h1.02
  text "Dielectric 5" at -194.008,73.085 h1.02
  text "PP-016" at -170.477,73.085 h1.02
  text "4.60mil" at -155.749,73.085 h1.02
  text "4.4" at -144.576,73.085 h1.02
  text "6" at -201.118,71.053 h1.02
  text "Layer 6 (PWR)" at -194.008,71.053 h1.02
  text "CF-004" at -170.477,71.053 h1.02
  text "1.38mil" at -155.749,71.053 h1.02
  text "Dielectric 6" at -194.008,69.021 h1.02
  text "FR-4 High TG" at -170.477,69.021 h1.02
  text "6.00mil" at -155.749,69.021 h1.02
  text "4.5" at -144.576,69.021 h1.02
  text "7" at -201.118,66.989 h1.02
  text "Layer 7 (GND)" at -194.008,66.989 h1.02
  text "CF-004" at -170.477,66.989 h1.02
  text "1.38mil" at -155.749,66.989 h1.02
  text "Dielectric 7" at -194.008,64.957 h1.02
  text "PP-016" at -170.477,64.957 h1.02
  text "4.60mil" at -155.749,64.957 h1.02
  text "4.4" at -144.576,64.957 h1.02
  text "8" at -201.118,62.925 h1.02
  text "Layer 8 (SIG/PWR)" at -194.008,62.925 h1.02
  text "CF-004" at -170.477,62.925 h1.02
  text "1.38mil" at -155.749,62.925 h1.02
  text "Dielectric 8" at -194.008,60.893 h1.02
  text "FR-4 High TG" at -170.477,60.893 h1.02
  text "6.00mil" at -155.749,60.893 h1.02
  text "4.5" at -144.576,60.893 h1.02
  text "9" at -201.118,58.861 h1.02
  text "Layer 9 (GND)" at -194.008,58.861 h1.02
  text "CF-004" at -170.477,58.861 h1.02
  text "1.38mil" at -155.749,58.861 h1.02
  text "Dielectric 9" at -194.008,56.829 h1.02
  text "PP-016" at -170.477,56.829 h1.02
  text "4.60mil" at -155.749,56.829 h1.02
  text "4.4" at -144.576,56.829 h1.02
  text "10" at -201.118,54.797 h1.02
  text "Bottom Layer (PAD/SIG)" at -194.008,54.797 h1.02
  text "CF-004" at -170.477,54.797 h1.02
  text "2.76mil" at -155.749,54.797 h1.02
  text "Bottom Solder" at -194.008,52.765 h1.02
  text "Solder Resist" at -170.477,52.765 h1.02
  text "0.40mil" at -155.749,52.765 h1.02
  text "3.5" at -144.576,52.765 h1.02
  text "Bottom Overlay" at -194.008,50.733 h1.02
  text ".Layer_Name" at -195.191,-114.202 h1.52
M13 Component Bodies Top:
  text ".Layer_Name" at -195.191,-114.202 h1.52
M14 Component Bodies Bottom:
  text ".Layer_Name" at -195.191,-114.202 h1.52
M15:
  lines w0.254: -147.522,-92.364 -147.522,7.648
  text ".Layer_Name" at -195.191,-114.202 h1.52
M16 Courtyards Bottom:
  text ".Layer_Name" at -195.191,-114.202 h1.52
Drill Drawing:
  circle w0.254: c-47.953,60.314 r0.339
  circle w0.254: c-47.953,60.314 r0.564
  circle w0.254: c-47.953,50.154 r0.564
  lines w0.254: -48.517,53.259 -47.388,53.259 -47.953,52.13 -48.517,53.259 ; -48.517,55.234 -47.953,54.67 -47.388,55.234 -47.953,55.799 -48.517,55.234 ; -48.517,57.21 -48.517,57.492 -48.235,57.774 -48.517,58.057 -48.517,58.339 -48.235,58.339 -47.953,58.057 -47.67,58.339 -47.388,58.339 -47.388,58.057 -47.67,57.774 -47.388,57.492 -47.388,57.21 -47.67,57.21 -47.953,57.492 -48.235,57.21 -48.517,57.21 ; -48.517,62.572 -48.235,62.572 -48.235,62.29 -47.67,62.29 -47.67,62.572 -47.388,62.572 -47.388,63.137 -47.67,63.137 -47.67,63.419 -48.235,63.419 -48.235,63.137 -48.517,63.137 -48.517,62.572 ; -48.517,64.83 -47.388,64.83 -47.388,65.959 -48.517,65.959 -48.517,64.83 ; -48.517,67.37 -47.953,67.652 -47.388,67.37 -47.67,67.934 -47.388,68.499 -47.953,68.217 -48.517,68.499 -48.235,67.934 -48.517,67.37
  lines w0.305: -49.556,48.828 81.031,48.828 ; -49.556,69.148 81.031,69.148 ; -39.957,46.288 -39.957,71.688 ; -28.784,46.288 -28.784,71.688 ; -5.727,46.288 -5.727,71.688 ; 3.11,46.288 3.11,71.688 ; 15.806,46.288 15.806,71.688 ; 61.682,46.288 61.682,71.688 ; -49.556,46.288 81.031,46.288 81.031,71.688 -49.556,71.688 -49.556,46.288
  text "Symbol" at -48.032,69.91 h1.22
  text "Quantity" at -39.195,69.91 h1.22
  text "Finished Hole Size" at -28.022,69.91 h1.22
  text "Plated" at -4.965,69.91 h1.22
  text "Hole Type" at 3.872,69.91 h1.22
  text "Drill Layer Pair" at 16.568,69.91 h1.22
  text "Hole Tolerance" at 62.444,69.91 h1.22
  text "2" at -39.195,67.37 h1.02
  text "106.30mil (2.700mm)" at -28.022,67.37 h1.02
  text "NPTH" at -4.965,67.37 h1.02
  text "Round" at 3.872,67.37 h1.02
  text "Top Layer (PADS/SIG) - Bottom Layer (PAD/SIG)" at 16.568,67.37 h1.02
  text "2" at -39.195,64.83 h1.02
  text "118.11mil (3.000mm)" at -28.022,64.83 h1.02
  text "NPTH" at -4.965,64.83 h1.02
  text "Round" at 3.872,64.83 h1.02
  text "Top Layer (PADS/SIG) - Bottom Layer (PAD/SIG)" at 16.568,64.83 h1.02
  text "280" at -39.195,62.29 h1.02
  text "7.87mil (0.200mm)" at -28.022,62.29 h1.02
  text "PTH" at -4.965,62.29 h1.02
  text "Round" at 3.872,62.29 h1.02
  text "Top Layer (PADS/SIG) - Bottom Layer (PAD/SIG)" at 16.568,62.29 h1.02
  text "943" at -39.195,59.75 h1.02
  text "8.00mil (0.203mm)" at -28.022,59.75 h1.02
  text "PTH" at -4.965,59.75 h1.02
  text "Round" at 3.872,59.75 h1.02
  text "Top Layer (PADS/SIG) - Bottom Layer (PAD/SIG)" at 16.568,59.75 h1.02
  text "21" at -39.195,57.21 h1.02
  text "31.89mil (0.810mm)" at -28.022,57.21 h1.02
  text "PTH" at -4.965,57.21 h1.02
  text "Round" at 3.872,57.21 h1.02
  text "Top Layer (PADS/SIG) - Bottom Layer (PAD/SIG)" at 16.568,57.21 h1.02
  text "+/-1.97mil" at 62.444,57.21 h1.02
  text "103" at -39.195,54.67 h1.02
  text "40.00mil (1.016mm)" at -28.022,54.67 h1.02
  text "PTH" at -4.965,54.67 h1.02
  text "Round" at 3.872,54.67 h1.02
  text "Top Layer (PADS/SIG) - Bottom Layer (PAD/SIG)" at 16.568,54.67 h1.02
  text "14" at -39.195,52.13 h1.02
  text "63.00mil (1.600mm)" at -28.022,52.13 h1.02
  text "PTH" at -4.965,52.13 h1.02
  text "Round" at 3.872,52.13 h1.02
  text "Top Layer (PADS/SIG) - Bottom Layer (PAD/SIG)" at 16.568,52.13 h1.02
  text "2" at -39.195,49.59 h1.02
  text "183.07mil (4.650mm)" at -28.022,49.59 h1.02
  text "PTH" at -4.965,49.59 h1.02
  text "Round" at 3.872,49.59 h1.02
  text "Top Layer (PADS/SIG) - Bottom Layer (PAD/SIG)" at 16.568,49.59 h1.02
  text "1367 Total" at -39.195,47.05 h1.02
  text ".Layer_Name" at -195.191,-114.202 h1.52
M17 Embedded Cavity:
  text ".Layer_Name" at -195.191,-114.202 h1.52
M18 Embedded Assembly:
  text ".Layer_Name" at -195.191,-114.202 h1.52
M19 Embedded Keepout:
  text ".Layer_Name" at -195.191,-114.202 h1.52

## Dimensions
-147.54,7.642 to 10.244,-92.396 on M2 Board Dimensions
-0.003,-84.71 to -0.003,-0.007 on M2 Board Dimensions
10.244,7.68 to -0.003,-0.007 on M2 Board Dimensions
-0.003,-0.007 to 10.117,7.642 on M2 Board Dimensions
-143.947,2.13 to -143.947,-86.77 on M2 Board Dimensions
-143.947,2.13 to -147.479,0.035 on M2 Board Dimensions
-143.947,2.13 to -0.005,7.68 on M2 Board Dimensions
-147.54,7.642 to -147.109,-1.629 on M2 Board Dimensions
-147.345,-83.087 to -147.526,-92.358 on M2 Board Dimensions
-147.246,-89.856 to -147.526,-92.358 on M2 Board Dimensions
-147.54,7.642 to -147.39,5.14 on M2 Board Dimensions
5.164,-75.136 to -0.003,-0.007 on M2 Board Dimensions
-147.515,7.68 to -0.003,-0.007 on M2 Board Dimensions
5.164,-75.136 to -0.003,-0.007 on M2 Board Dimensions
10.244,-92.396 to -147.515,-92.396 on M2 Board Dimensions
-0.003,-0.007 to 10.117,7.642 on M2 Board Dimensions
-189.781,-83.187 to -190.162,-1.78 on M2 Board Dimensions
-147.246,-89.856 to -147.39,5.14 on M2 Board Dimensions
-147.54,7.642 to -147.526,-92.358 on M2 Board Dimensions
-209.847,-102.556 to -184.447,-102.556 on M2 Board Dimensions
